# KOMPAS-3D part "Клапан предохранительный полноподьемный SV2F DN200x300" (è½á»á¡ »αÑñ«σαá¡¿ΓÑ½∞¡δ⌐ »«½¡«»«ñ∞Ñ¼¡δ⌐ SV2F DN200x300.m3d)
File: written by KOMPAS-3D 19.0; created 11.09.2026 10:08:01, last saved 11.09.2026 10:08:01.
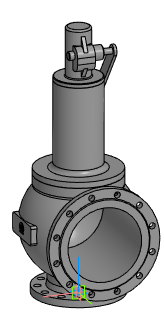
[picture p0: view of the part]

Document properties: Автор: elist; Организация: HP; Полное имя файла: Z:\3.Личные\sachek\Dendor\_3D для проектировщиков\5.9 SV2F. Клапан предохранительный полноподьемный\SV2F_STP\Клапан предохранительный полноподьемный SV2F DN200x300.m3d

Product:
- Part/product: Клапан предохранительный полноподьемный SV2F DN200x300

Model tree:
1. Операция без истории:1  (labels: Клапан предохранительный полноподьемный SV2F DN200x300)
